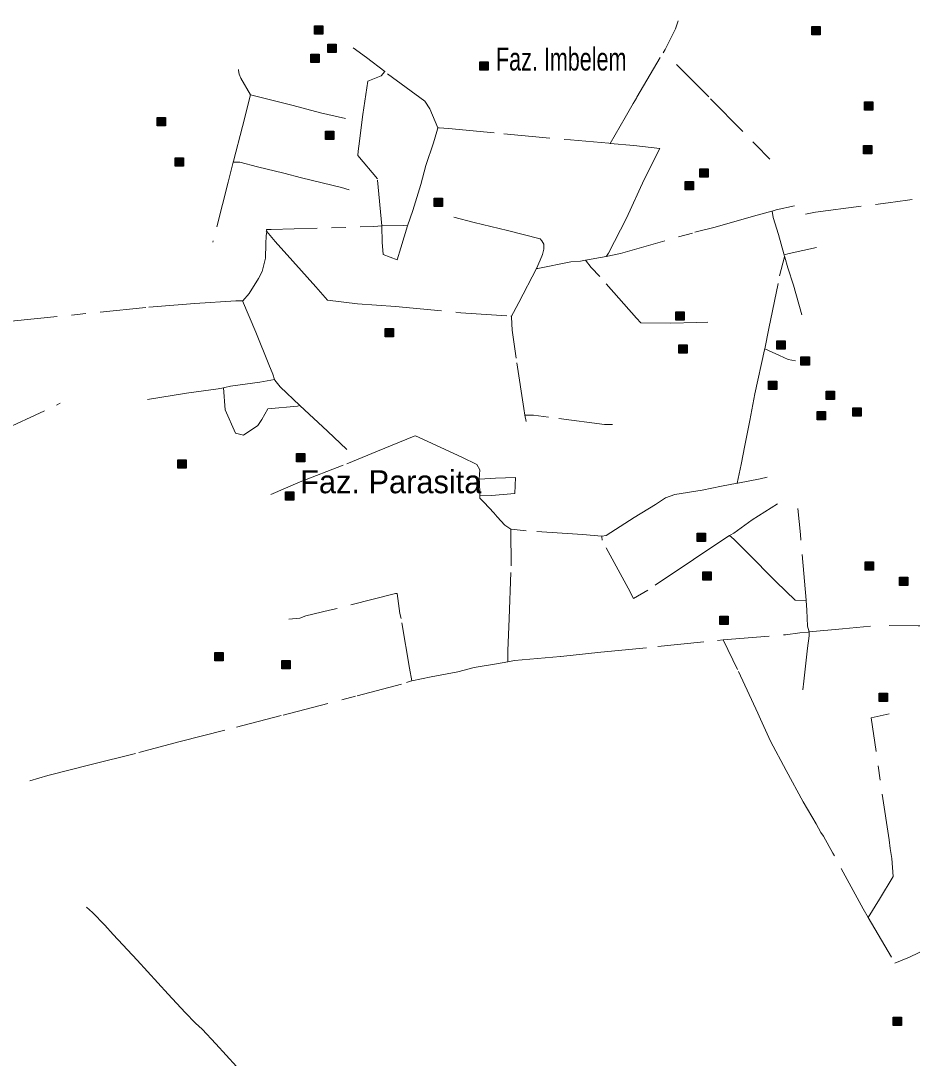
# Model space of a CAD drawing. Extents: x 393.5 to 446.9, y 8064.8 to 8120.4.
# Drawn here: x 399.75 to 405.95, y 8072.89 to 8080.11 of the extents above; entities that cross this region are included whole.
import ezdxf

# ---------------------------------------------------------------- set-up
doc = ezdxf.new("R2010")
doc.units = 0
doc.header["$LTSCALE"] = 0.064
doc.linetypes.add('DOT_DASHED', pattern=[7.7, 5, -1.2, 0.3, -1.2])
doc.layers.add('2', color=7, linetype='Continuous', lineweight=25)
doc.layers.add('22', color=7, linetype='DOT_DASHED', lineweight=13)
doc.layers.add('61', color=7, linetype='Continuous')

msp = doc.modelspace()

# ---------------------------------------------------------------- hatches: boundary and pattern name
at = {"layer": '2'}
for points in [[(401.7952, 8080.0776), (401.8532, 8080.0776), (401.8532, 8080.0196), (401.7952, 8080.0196)], [(405.2527, 8080.0725), (405.3107, 8080.0725), (405.3107, 8080.0145), (405.2527, 8080.0145)], [(401.8888, 8079.95), (401.9468, 8079.95), (401.9468, 8079.892), (401.8888, 8079.892)], [(401.77, 8079.8792), (401.828, 8079.8792), (401.828, 8079.8212), (401.77, 8079.8212)], [(402.9445, 8079.8274), (403.0025, 8079.8274), (403.0025, 8079.7694), (402.9445, 8079.7694)], [(405.6186, 8079.5486), (405.6766, 8079.5486), (405.6766, 8079.4906), (405.6186, 8079.4906)], [(400.7004, 8079.4393), (400.7584, 8079.4393), (400.7584, 8079.3813), (400.7004, 8079.3813)], [(401.8714, 8079.3454), (401.9294, 8079.3454), (401.9294, 8079.2874), (401.8714, 8079.2874)], [(405.6127, 8079.2457), (405.6707, 8079.2457), (405.6707, 8079.1877), (405.6127, 8079.1877)], [(400.8263, 8079.1591), (400.8843, 8079.1591), (400.8843, 8079.1011), (400.8263, 8079.1011)], [(404.473, 8079.0817), (404.531, 8079.0817), (404.531, 8079.0237), (404.473, 8079.0237)], [(404.3714, 8078.9938), (404.4294, 8078.9938), (404.4294, 8078.9358), (404.3714, 8078.9358)], [(402.6262, 8078.8785), (402.6842, 8078.8785), (402.6842, 8078.8205), (402.6262, 8078.8205)], [(404.3073, 8078.0887), (404.3653, 8078.0887), (404.3653, 8078.0307), (404.3073, 8078.0307)], [(402.2862, 8077.9723), (402.3442, 8077.9723), (402.3442, 8077.9143), (402.2862, 8077.9143)], [(404.3281, 8077.8573), (404.3861, 8077.8573), (404.3861, 8077.7993), (404.3281, 8077.7993)], [(405.0091, 8077.8855), (405.0671, 8077.8855), (405.0671, 8077.8275), (405.0091, 8077.8275)], [(405.1772, 8077.7739), (405.2352, 8077.7739), (405.2352, 8077.7159), (405.1772, 8077.7159)], [(404.9511, 8077.605), (405.0091, 8077.605), (405.0091, 8077.547), (404.9511, 8077.547)], [(405.353, 8077.5347), (405.411, 8077.5347), (405.411, 8077.4767), (405.353, 8077.4767)], [(405.5366, 8077.4204), (405.5946, 8077.4204), (405.5946, 8077.3624), (405.5366, 8077.3624)], [(405.289, 8077.3945), (405.347, 8077.3945), (405.347, 8077.3365), (405.289, 8077.3365)], [(400.8454, 8077.0579), (400.9034, 8077.0579), (400.9034, 8076.9999), (400.8454, 8076.9999)], [(401.6701, 8077.1016), (401.7281, 8077.1016), (401.7281, 8077.0436), (401.6701, 8077.0436)], [(401.593, 8076.8352), (401.651, 8076.8352), (401.651, 8076.7772), (401.593, 8076.7772)], [(404.4546, 8076.5489), (404.5126, 8076.5489), (404.5126, 8076.4909), (404.4546, 8076.4909)], [(405.6234, 8076.3492), (405.6814, 8076.3492), (405.6814, 8076.2912), (405.6234, 8076.2912)], [(404.4943, 8076.2799), (404.5523, 8076.2799), (404.5523, 8076.2219), (404.4943, 8076.2219)], [(405.8617, 8076.2414), (405.9197, 8076.2414), (405.9197, 8076.1834), (405.8617, 8076.1834)], [(404.6133, 8075.9711), (404.6713, 8075.9711), (404.6713, 8075.9131), (404.6133, 8075.9131)], [(401.1031, 8075.7173), (401.1611, 8075.7173), (401.1611, 8075.6593), (401.1031, 8075.6593)], [(401.5672, 8075.6616), (401.6252, 8075.6616), (401.6252, 8075.6036), (401.5672, 8075.6036)], [(405.7216, 8075.4341), (405.7796, 8075.4341), (405.7796, 8075.3761), (405.7216, 8075.3761)], [(405.8174, 8073.1812), (405.8754, 8073.1812), (405.8754, 8073.1232), (405.8174, 8073.1232)]]:
    msp.add_hatch(color=256, dxfattribs=at).paths.add_polyline_path(points)

# ---------------------------------------------------------------- linework, layer by layer
for points in [[(401.7952, 8080.0776), (401.8532, 8080.0776), (401.8532, 8080.0196), (401.7952, 8080.0196)], [(405.2527, 8080.0725), (405.3107, 8080.0725), (405.3107, 8080.0145), (405.2527, 8080.0145)], [(401.8888, 8079.95), (401.9468, 8079.95), (401.9468, 8079.892), (401.8888, 8079.892)], [(401.77, 8079.8792), (401.828, 8079.8792), (401.828, 8079.8212), (401.77, 8079.8212)], [(402.9445, 8079.8274), (403.0025, 8079.8274), (403.0025, 8079.7694), (402.9445, 8079.7694)], [(405.6186, 8079.5486), (405.6766, 8079.5486), (405.6766, 8079.4906), (405.6186, 8079.4906)], [(400.7004, 8079.4393), (400.7584, 8079.4393), (400.7584, 8079.3813), (400.7004, 8079.3813)], [(401.8714, 8079.3454), (401.9294, 8079.3454), (401.9294, 8079.2874), (401.8714, 8079.2874)], [(405.6127, 8079.2457), (405.6707, 8079.2457), (405.6707, 8079.1877), (405.6127, 8079.1877)], [(400.8263, 8079.1591), (400.8843, 8079.1591), (400.8843, 8079.1011), (400.8263, 8079.1011)], [(404.473, 8079.0817), (404.531, 8079.0817), (404.531, 8079.0237), (404.473, 8079.0237)], [(404.3714, 8078.9938), (404.4294, 8078.9938), (404.4294, 8078.9358), (404.3714, 8078.9358)], [(402.6262, 8078.8785), (402.6842, 8078.8785), (402.6842, 8078.8205), (402.6262, 8078.8205)], [(404.3073, 8078.0887), (404.3653, 8078.0887), (404.3653, 8078.0307), (404.3073, 8078.0307)], [(402.2862, 8077.9723), (402.3442, 8077.9723), (402.3442, 8077.9143), (402.2862, 8077.9143)], [(404.3281, 8077.8573), (404.3861, 8077.8573), (404.3861, 8077.7993), (404.3281, 8077.7993)], [(405.0091, 8077.8855), (405.0671, 8077.8855), (405.0671, 8077.8275), (405.0091, 8077.8275)], [(405.1772, 8077.7739), (405.2352, 8077.7739), (405.2352, 8077.7159), (405.1772, 8077.7159)], [(404.9511, 8077.605), (405.0091, 8077.605), (405.0091, 8077.547), (404.9511, 8077.547)], [(405.353, 8077.5347), (405.411, 8077.5347), (405.411, 8077.4767), (405.353, 8077.4767)], [(405.5366, 8077.4204), (405.5946, 8077.4204), (405.5946, 8077.3624), (405.5366, 8077.3624)], [(405.289, 8077.3945), (405.347, 8077.3945), (405.347, 8077.3365), (405.289, 8077.3365)], [(400.8454, 8077.0579), (400.9034, 8077.0579), (400.9034, 8076.9999), (400.8454, 8076.9999)], [(401.6701, 8077.1016), (401.7281, 8077.1016), (401.7281, 8077.0436), (401.6701, 8077.0436)], [(401.593, 8076.8352), (401.651, 8076.8352), (401.651, 8076.7772), (401.593, 8076.7772)], [(404.4546, 8076.5489), (404.5126, 8076.5489), (404.5126, 8076.4909), (404.4546, 8076.4909)], [(405.6234, 8076.3492), (405.6814, 8076.3492), (405.6814, 8076.2912), (405.6234, 8076.2912)], [(404.4943, 8076.2799), (404.5523, 8076.2799), (404.5523, 8076.2219), (404.4943, 8076.2219)], [(405.8617, 8076.2414), (405.9197, 8076.2414), (405.9197, 8076.1834), (405.8617, 8076.1834)], [(404.6133, 8075.9711), (404.6713, 8075.9711), (404.6713, 8075.9131), (404.6133, 8075.9131)], [(401.1031, 8075.7173), (401.1611, 8075.7173), (401.1611, 8075.6593), (401.1031, 8075.6593)], [(401.5672, 8075.6616), (401.6252, 8075.6616), (401.6252, 8075.6036), (401.5672, 8075.6036)], [(405.7216, 8075.4341), (405.7796, 8075.4341), (405.7796, 8075.3761), (405.7216, 8075.3761)], [(405.8174, 8073.1812), (405.8754, 8073.1812), (405.8754, 8073.1232), (405.8174, 8073.1232)]]:
    msp.add_lwpolyline(points, close=True, dxfattribs=at)
at = {"layer": '22'}
for p, q in [((401.2306, 8079.1289), (401.2326, 8079.1367)), ((402.7632, 8078.7453), (402.9051, 8078.7089)), ((401.4592, 8078.6507), (401.4627, 8078.6466)), ((401.461, 8078.6598), (401.4629, 8078.6598)), ((405.063, 8078.4706), (405.0639, 8078.4676)), ((403.3383, 8078.3883), (403.3469, 8078.39)), ((404.9238, 8077.824), (404.925, 8077.8302)), ((401.162, 8077.5597), (401.1711, 8077.5617)), ((403.2569, 8077.3683), (403.2568, 8077.3691)), ((405.2337, 8075.8607), (405.2342, 8075.8607))]:
    msp.add_line(p, q, dxfattribs=at)
for points in [[(404.0329, 8079.573), (404.0369, 8079.58), (404.2187, 8079.8902), (404.2336, 8079.9119), (404.3056, 8080.0561), (404.3228, 8080.1126)], [(402.283, 8079.7587), (402.1558, 8079.8573), (402.0629, 8079.9246)], [(404.3109, 8079.8086), (404.5492, 8079.5705), (404.8619, 8079.2507), (404.9615, 8079.1486)], [(401.3498, 8079.5964), (401.2828, 8079.7143), (401.2705, 8079.7407), (401.2669, 8079.7671), (401.2669, 8079.7742)], [(402.1041, 8079.239), (402.1321, 8079.46), (402.1665, 8079.6919), (402.2595, 8079.73), (402.283, 8079.7587)], [(402.6516, 8079.367), (402.5977, 8079.4995), (402.5613, 8079.5541), (402.2846, 8079.7575), (402.283, 8079.7587)], [(401.2326, 8079.1367), (401.2948, 8079.3767), (401.3498, 8079.5964)], [(402.0115, 8079.4315), (401.8376, 8079.4716), (401.6476, 8079.5224), (401.3498, 8079.5964)], [(403.8495, 8079.2594), (403.9555, 8079.4399), (404.0098, 8079.5361), (404.0329, 8079.573)], [(402.4412, 8078.6848), (402.4418, 8078.6864), (402.4777, 8078.7923), (402.5341, 8078.9741), (402.5687, 8079.105), (402.6223, 8079.2632), (402.6451, 8079.3413), (402.6516, 8079.367), (402.6559, 8079.3668), (402.6615, 8079.3665)], [(402.6615, 8079.3665), (402.7262, 8079.3633), (403.1116, 8079.3253), (403.5739, 8079.2835), (403.8403, 8079.2602), (403.8495, 8079.2594)], [(402.2629, 8078.6848), (402.232, 8079.013), (402.0955, 8079.1748), (402.0991, 8079.2058), (402.1041, 8079.239)], [(403.8495, 8079.2594), (404.016, 8079.2438), (404.1962, 8079.2238), (404.0879, 8079.0074), (403.9651, 8078.74), (403.8383, 8078.4946), (403.8258, 8078.4757), (403.8238, 8078.4727)], [(401.2306, 8079.1289), (401.1944, 8078.9895), (401.0884, 8078.5732)], [(402.0356, 8078.9369), (401.9821, 8078.9529), (401.7038, 8079.0197), (401.5807, 8079.0518), (401.3988, 8079.0973), (401.2758, 8079.1295), (401.2306, 8079.1289)], [(405.2075, 8078.7664), (405.2789, 8078.7819), (405.7836, 8078.846), (405.917, 8078.8654), (405.951, 8078.8695)], [(403.8238, 8078.4727), (403.922, 8078.4927), (404.4403, 8078.6413), (404.5805, 8078.6776), (404.8462, 8078.7522), (404.9749, 8078.7879), (404.9772, 8078.7886)], [(405.1324, 8078.826), (405.0048, 8078.7971), (404.9772, 8078.7886)], [(404.9772, 8078.7886), (404.9827, 8078.7431), (405.0209, 8078.6249), (405.0571, 8078.4922), (405.0592, 8078.4845), (405.063, 8078.4706)], [(401.2954, 8078.164), (401.2963, 8078.1651), (401.3409, 8078.2161), (401.4064, 8078.3197), (401.4301, 8078.3688), (401.4538, 8078.4615), (401.4556, 8078.5616), (401.4598, 8078.6162), (401.4627, 8078.6466), (401.461, 8078.6598)], [(401.4627, 8078.6466), (401.5211, 8078.5779), (401.6448, 8078.4397), (401.805, 8078.2615), (401.8859, 8078.1687), (402.0951, 8078.1433), (402.359, 8078.1251), (402.8131, 8078.0815), (403.1593, 8078.0581), (403.1596, 8078.0581), (403.1635, 8078.0578)], [(401.4629, 8078.6598), (401.4938, 8078.6598), (402.2083, 8078.6812), (402.2629, 8078.6848)], [(402.4412, 8078.6848), (402.4139, 8078.6885), (402.263, 8078.6848), (402.2629, 8078.6848)], [(402.2629, 8078.6848), (402.2629, 8078.6845), (402.263, 8078.683)], [(402.263, 8078.683), (402.2665, 8078.5721), (402.272, 8078.4866), (402.3702, 8078.4484), (402.3957, 8078.5321), (402.4412, 8078.6848)], [(402.9051, 8078.7089), (403.1362, 8078.6543), (403.3628, 8078.5944), (403.3755, 8078.5816), (403.3883, 8078.558), (403.3901, 8078.5235), (403.3792, 8078.4853), (403.3646, 8078.4471), (403.3383, 8078.3883)], [(405.2849, 8078.5359), (405.0956, 8078.4941), (405.0592, 8078.4845)], [(403.3469, 8078.39), (403.5766, 8078.4345), (403.644, 8078.44), (403.68, 8078.4473)], [(403.68, 8078.4473), (403.6802, 8078.4473), (403.8238, 8078.4727)], [(404.5305, 8078.016), (404.4537, 8078.0131), (404.2696, 8078.0086), (404.0642, 8078.0103), (404.0344, 8078.043), (403.7776, 8078.3326), (403.7194, 8078.3962), (403.68, 8078.4473)], [(404.925, 8077.8302), (404.9532, 8077.9722), (405.0283, 8078.3377), (405.063, 8078.4706)], [(405.0639, 8078.4676), (405.0849, 8078.3942), (405.1249, 8078.2723), (405.1832, 8078.067)], [(403.3383, 8078.3883), (403.2155, 8078.1533), (403.1791, 8078.0824), (403.1635, 8078.0578)], [(401.2954, 8078.164), (401.2481, 8078.164), (400.9625, 8078.1446), (400.6223, 8078.1184), (399.6165, 8078.0147)], [(401.5168, 8077.6157), (401.5047, 8077.6549), (401.4774, 8077.7203), (401.3883, 8077.9458), (401.2954, 8078.164)], [(403.1963, 8077.7649), (403.1681, 8077.9612), (403.1638, 8078.0516), (403.1635, 8078.0578)], [(404.9238, 8077.824), (404.8565, 8077.5164), (404.8219, 8077.3309), (404.7863, 8077.1587), (404.7617, 8077.0264), (404.7339, 8076.8956)], [(404.925, 8077.8302), (405.0283, 8077.7844), (405.0883, 8077.7553), (405.1393, 8077.7462)], [(403.2568, 8077.3691), (403.2501, 8077.4161), (403.1963, 8077.7649)], [(401.1711, 8077.5617), (401.2111, 8077.5706), (401.4149, 8077.5979), (401.5167, 8077.6157), (401.5168, 8077.6157)], [(401.6931, 8077.4352), (401.5568, 8077.5666), (401.5195, 8077.6124), (401.5168, 8077.6157)], [(400.6338, 8077.478), (400.9045, 8077.5211), (401.1247, 8077.552), (401.162, 8077.5597)], [(401.6931, 8077.4352), (401.676, 8077.4308), (401.4713, 8077.4124), (401.4295, 8077.3396), (401.4004, 8077.2978), (401.3003, 8077.2305), (401.2457, 8077.2433), (401.1729, 8077.4051), (401.162, 8077.5594), (401.162, 8077.5597)], [(399.5962, 8077.2501), (399.6284, 8077.2642), (400.0008, 8077.4378), (400.0259, 8077.4532)], [(401.6931, 8077.4352), (401.8852, 8077.2569), (402.0204, 8077.1306)], [(403.8678, 8077.303), (403.8114, 8077.303), (403.422, 8077.3539), (403.3182, 8077.3684), (403.2569, 8077.3683), (403.2655, 8077.3248)], [(401.4909, 8076.8166), (401.6948, 8076.9057), (402.0187, 8077.0294), (402.2334, 8077.1185), (402.489, 8077.2221), (402.4981, 8077.2258), (402.5837, 8077.1858), (402.8184, 8077.0766), (402.923, 8077.0258), (402.9449, 8076.9876), (402.9404, 8076.9225)], [(402.9477, 8076.813), (403.0259, 8076.8094), (403.1878, 8076.8239), (403.1915, 8076.9348), (403.0532, 8076.9294), (402.9411, 8076.9225), (402.9404, 8076.9225)], [(402.9404, 8076.9225), (402.9406, 8076.9202), (402.9407, 8076.9197)], [(402.9407, 8076.9197), (402.9415, 8076.9107), (402.9445, 8076.8131), (402.9477, 8076.813)], [(404.9429, 8076.9382), (404.8938, 8076.9255), (404.7387, 8076.8965), (404.7339, 8076.8956)], [(403.7928, 8076.5264), (403.8226, 8076.531), (404.0166, 8076.6571), (404.166, 8076.7463), (404.2352, 8076.794), (404.2999, 8076.8171), (404.4891, 8076.8464), (404.6246, 8076.8741), (404.7339, 8076.8956)], [(402.9749, 8076.7603), (402.9452, 8076.7903), (402.9445, 8076.8131)], [(403.1604, 8076.5754), (403.1185, 8076.6045), (403.0657, 8076.6626), (403.0422, 8076.6895), (402.9749, 8076.7603)], [(405.0131, 8076.7524), (404.8384, 8076.6397), (404.7092, 8076.5487), (404.684, 8076.533), (404.6838, 8076.5329), (404.6801, 8076.5306)], [(405.2126, 8076.0817), (405.1737, 8076.5386), (405.155, 8076.7197)], [(403.1393, 8075.6524), (403.1384, 8075.7299), (403.1483, 8075.954), (403.1612, 8076.3206), (403.1604, 8076.5681), (403.1604, 8076.5754)], [(403.7921, 8076.5265), (403.659, 8076.539), (403.2677, 8076.5644), (403.1629, 8076.5751), (403.1604, 8076.5754)], [(404.6801, 8076.5306), (404.6055, 8076.4834), (404.429, 8076.3652), (404.1123, 8076.1506), (404.0123, 8076.0943), (403.9759, 8076.1652), (403.7946, 8076.4991), (403.793, 8076.5234), (403.7928, 8076.5264), (403.7921, 8076.5265)], [(405.2129, 8076.0783), (405.1365, 8076.082), (405.005, 8076.2087), (404.8003, 8076.4152), (404.7111, 8076.5052), (404.6801, 8076.5306)], [(402.3968, 8075.9545), (402.3892, 8075.9899), (402.3693, 8076.1288), (402.3585, 8076.1288), (401.8984, 8076.0111), (401.7355, 8075.9736), (401.694, 8075.9556), (401.6163, 8075.9484)], [(405.2342, 8075.8607), (405.222, 8075.9001), (405.2184, 8076.0129), (405.2129, 8076.0783), (405.2129, 8076.0785), (405.2126, 8076.0817)], [(402.4715, 8075.5202), (402.4553, 8075.6086), (402.3968, 8075.9545)], [(405.2342, 8075.8607), (405.4652, 8075.8812), (405.6603, 8075.9011)], [(405.7894, 8075.9053), (405.9912, 8075.9023), (406.3547, 8075.906), (406.3767, 8075.9062)], [(404.6365, 8075.8056), (405.0695, 8075.8407), (405.1695, 8075.855), (405.2273, 8075.8601), (405.2337, 8075.8607)], [(405.2342, 8075.8607), (405.2345, 8075.8338), (405.2236, 8075.7483), (405.1968, 8075.5185), (405.1908, 8075.4574)], [(403.1393, 8075.6524), (403.1861, 8075.6626), (403.5075, 8075.6901), (403.7854, 8075.7206), (404.1829, 8075.7583), (404.5956, 8075.8018), (404.6365, 8075.8056)], [(404.8779, 8075.296), (404.7362, 8075.5994), (404.6365, 8075.8056)], [(402.4715, 8075.5202), (402.607, 8075.549), (402.7912, 8075.5833), (402.9049, 8075.6122), (403.0602, 8075.6392), (403.1393, 8075.6524)], [(399.8169, 8074.8255), (399.9414, 8074.8616), (400.2412, 8074.9374), (400.5745, 8075.0209), (400.862, 8075.0979), (401.2532, 8075.1987), (401.5775, 8075.2828), (402.0907, 8075.4153), (402.4352, 8075.5079), (402.4704, 8075.5198), (402.4705, 8075.5198), (402.4715, 8075.5202)], [(405.3154, 8074.4657), (405.282, 8074.526), (405.1928, 8074.6787), (405.0734, 8074.897), (404.966, 8075.1007), (404.8968, 8075.2535), (404.8779, 8075.296)], [(405.7975, 8074.3536), (405.7896, 8074.4146), (405.664, 8075.262), (405.7896, 8075.2903)], [(405.6433, 8073.8752), (405.6098, 8073.934), (405.3994, 8074.3213), (405.3339, 8074.4409), (405.3154, 8074.4657)], [(405.6433, 8073.8752), (405.7239, 8074.0012), (405.8185, 8074.1594), (405.8076, 8074.2849), (405.7975, 8074.3536)], [(400.2108, 8073.9456), (400.2513, 8073.9088), (400.3372, 8073.8208), (400.3953, 8073.7556)], [(405.6433, 8073.8752), (405.8306, 8073.5561), (405.9325, 8073.5979), (406.2237, 8073.7398), (406.6104, 8073.918), (406.6461, 8073.9439)], [(400.3953, 8073.7556), (400.5624, 8073.5778), (400.7786, 8073.3405), (400.8965, 8073.2136), (400.9678, 8073.1379)], [(400.9678, 8073.1379), (401.0131, 8073.0964), (401.1088, 8072.9953), (401.3483, 8072.7336), (401.4845, 8072.5847), (401.5284, 8072.5274)]]:
    msp.add_lwpolyline(points, dxfattribs=at)

# ---------------------------------------------------------------- texts
at = {"layer": '61', "width": 0.7}
msp.add_text('Faz. Imbelem', height=0.16, dxfattribs=at).set_placement((403.0567, 8079.7664))
at = {"layer": '61'}
msp.add_text('Faz. Parasita', height=0.16, dxfattribs=at).set_placement((401.695, 8076.8256))

doc.saveas('drawing.dxf')
